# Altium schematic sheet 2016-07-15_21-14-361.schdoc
size 469 x 147 mm; SheetNumber: 1; SheetTotal: 1
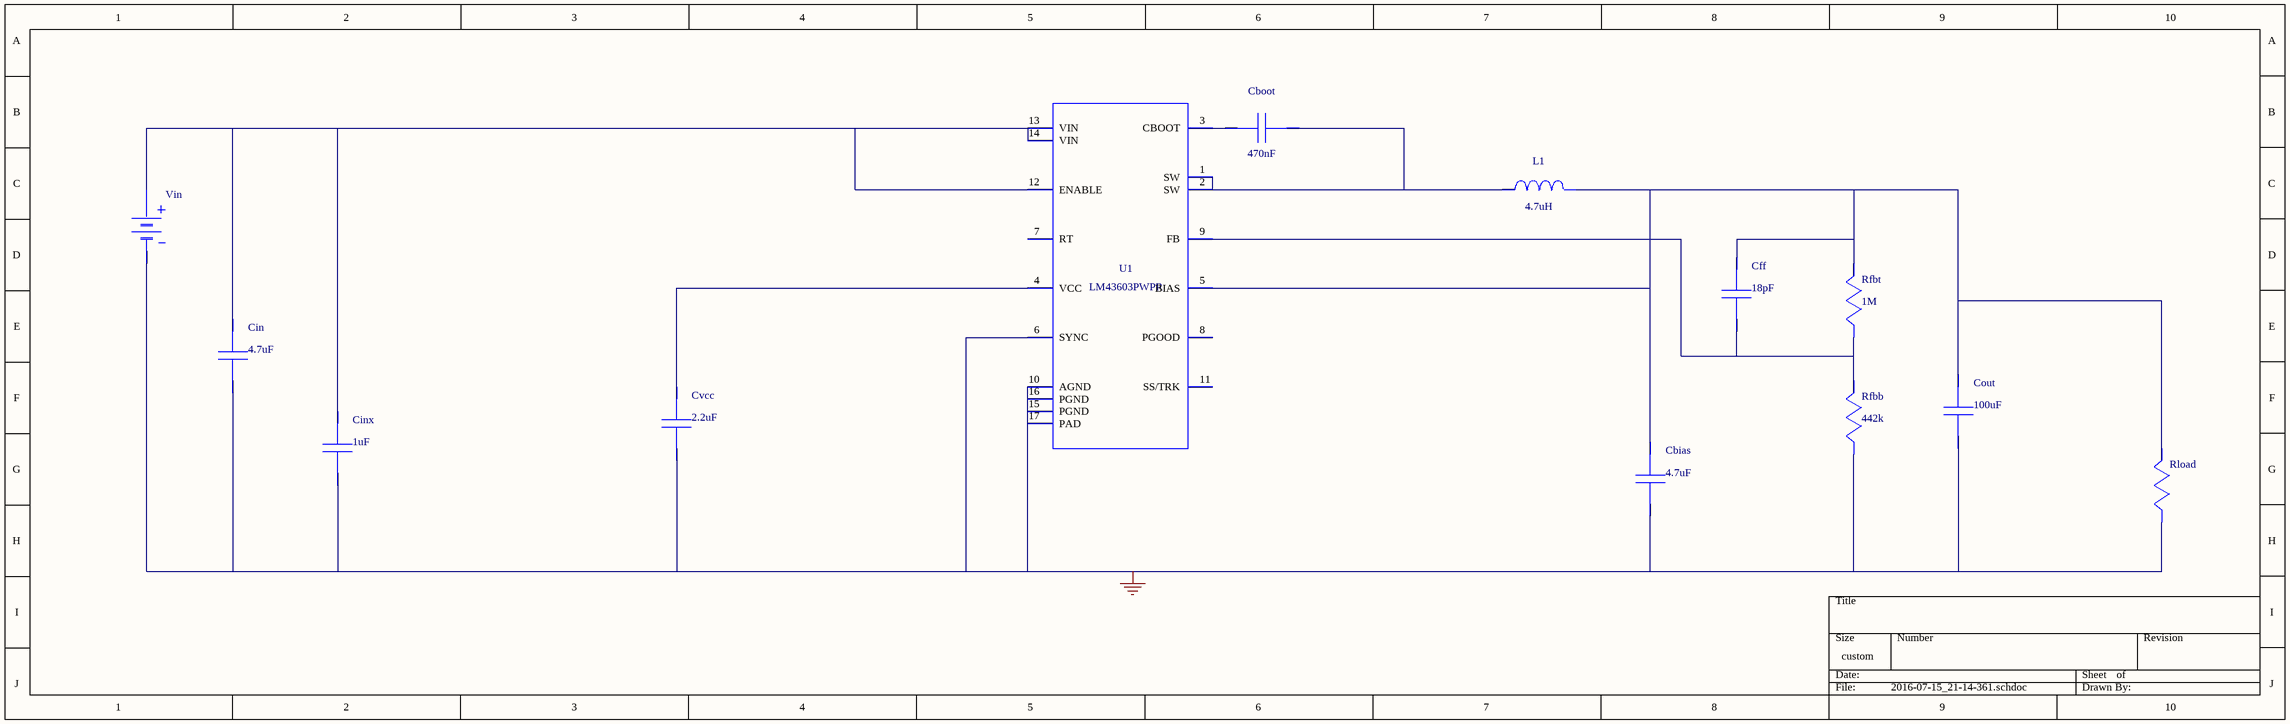
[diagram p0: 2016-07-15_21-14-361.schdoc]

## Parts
Cbias  value 4.7uF  (hidden comment: GRM188R60J475KE19D)
Cboot  value 470nF  (hidden comment: GRM155C80J474KE19D)
Cff  value 18pF  (hidden comment: C0805C180M3GACTU)
Cin  value 4.7uF  (hidden comment: GRM32ER71H475KA88L)
Cinx  value 1uF  (hidden comment: GRM188R61C105KA93D)
Cout  value 100uF  (hidden comment: GRM31CR60J107ME39L)
Cvcc  value 2.2uF  (hidden comment: GRM155R60J225ME15D)
L1  value 4.7uH  (hidden comment: SRN8040-4R7Y)
Rfbb  value 442k  (hidden comment: CRCW0402442KFKED)
Rfbt  value 1M  (hidden comment: CRCW04021M00FKED)
Rload  WB_LOAD_RESISTOR  (value not drawn)
U1  LM43603PWPR
Vin  WB_BATTERY  (value not drawn)

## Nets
0: Cbias.2 Cin.2 Cinx.2 Cout.2 Cvcc.2 Rfbb.2 Rload.2 U1.6(SYNC) U1.10(AGND) U1.15(PGND) U1.16(PGND) U1.17(PAD) Vin.2(-)
NetCbias_1: Cbias.1 Cff.1 Cout.1 L1.2 Rfbt.1 Rload.1 U1.5(BIAS)
NetCboot_1: Cboot.1 L1.1 U1.1(SW) U1.2(SW)
NetCboot_2: Cboot.2 U1.3(CBOOT)
NetCff_2: Cff.2 Rfbb.1 Rfbt.2 U1.9(FB)
NetCin_1: Cin.1 Cinx.1 U1.12(ENABLE) U1.13(VIN) U1.14(VIN) Vin.1(+)
NetCvcc_1: Cvcc.1 U1.4(VCC)

Not connected (* = marked no-connect by the designer): U1 7(RT) 8(PGOOD) 11(SS/TRK)

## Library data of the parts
Cbias = GRM188R60J475KE19D: GRM188R60J475KE1; Manufacturer Name: MuRata
Cboot = GRM155C80J474KE19D: GRM155C80J474KE1; Manufacturer Name: MuRata
Cff = C0805C180M3GACTU: Manufacturer Name: Kemet
Cin = GRM32ER71H475KA88L: GRM32ER71H475KA8; Manufacturer Name: MuRata
Cinx = GRM188R61C105KA93D: GRM188R61C105KA9; Manufacturer Name: MuRata
Cout = GRM31CR60J107ME39L: GRM31CR60J107ME3; Manufacturer Name: MuRata
Cvcc = GRM155R60J225ME15D: GRM155R60J225ME1; Manufacturer Name: MuRata
L1 = SRN8040-4R7Y: Manufacturer Name: Bourns
Rfbb = CRCW0402442KFKED: Manufacturer Name: Vishay-Dale
Rfbt = CRCW04021M00FKED: Manufacturer Name: Vishay-Dale
U1 = LM43603PWPR: Manufacturer Name: Texas Instruments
